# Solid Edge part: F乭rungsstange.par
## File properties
Username: bmolnar
Dokumentum tartalom típus: 0
Author: bmolnar
Last saved by: bmolnar
Revision: 78
Sűrűség: 0,000 kg/m^3
Pontosság: 0,990
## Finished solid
Body 1: solid body, 8 faces, 7 edges, 5 vertices.
  Faces by surface: cone 4, cylinder 2, plane 2
  Edges by curve: circle 7
Bounding box of the edges (mm): 8.000 x 8.000 x 62.000, from (-4, -4, -36) to (4, 4, 26).
Cylindrical faces by radius (mm): R2.067 x1, R4 x1
Conical faces (half-angle, radius in mm at the cone's reference point): 45 deg R2.217 x1, 45 deg R3.5 x1, 45 deg R3.9 x1, 59 deg R1.0335 x1
Planar faces by outward normal: +z 1, -z 1
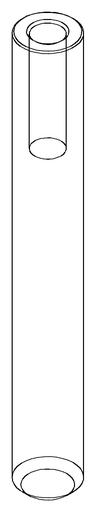
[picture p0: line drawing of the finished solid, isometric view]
